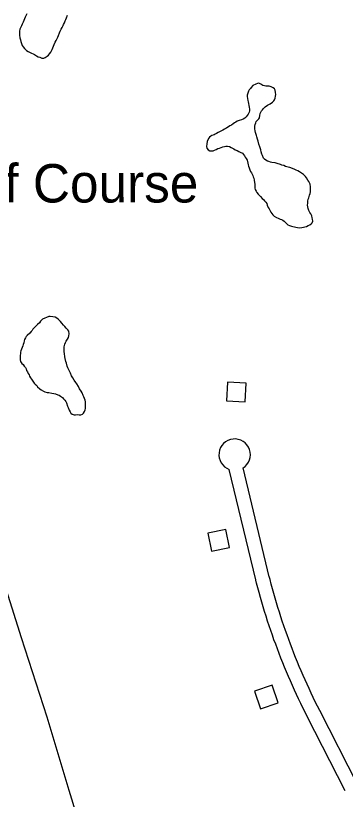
# Model space of a CAD drawing. Extents: x 3683402 to 3721514, y 487807 to 513565.
# Drawn here: x 3691713 to 3692425, y 494928 to 496621 of the extents above; entities that cross this region are included whole.
import ezdxf

# ---------------------------------------------------------------- set-up
doc = ezdxf.new("R2010")
doc.units = 0
for name, color, linetype in [('V-BLDG-IDEN', 7, 'Continuous'), ('V-BLDG-OTLN', 7, 'Continuous'), ('V-ROAD-CNTR', 7, 'Continuous'), ('V-TOPO-SHOR', 7, 'Continuous')]:
    doc.layers.add(name, color=color, linetype=linetype)

msp = doc.modelspace()

# ---------------------------------------------------------------- linework, layer by layer
at = {"layer": 'V-BLDG-OTLN'}
for points in [[(3692168.7, 495789), (3692208.7, 495786.7), (3692210.9, 495826.7), (3692171, 495828.9)], [(3692175.2, 495471.9), (3692167.3, 495511.1), (3692128.1, 495503.1), (3692136, 495463.9)], [(3692280.3, 495136.3), (3692267.3, 495174.1), (3692229.4, 495161.2), (3692242.4, 495123.3)]]:
    msp.add_lwpolyline(points, close=True, dxfattribs=at)
at = {"layer": 'V-ROAD-CNTR'}
for points in [[(3692231.8, 495401.8), (3692174.2, 495640.7)], [(3692261, 495408.8), (3692204.3, 495643.8)], [(3692343.3, 495106.4), (3692338.5, 495115.9), (3692333.7, 495125.5), (3692329.1, 495135), (3692324.4, 495144.7), (3692319.9, 495154.3), (3692315.4, 495164), (3692311, 495173.7), (3692306.7, 495183.5), (3692302.5, 495193.3), (3692298.3, 495203.1), (3692294.2, 495213), (3692290.2, 495222.9), (3692286.3, 495232.8), (3692282.4, 495242.7), (3692278.6, 495252.7), (3692274.9, 495262.7), (3692271.2, 495272.7), (3692267.7, 495282.8), (3692264.2, 495292.9), (3692260.8, 495303), (3692257.4, 495313.1), (3692254.2, 495323.3), (3692251, 495333.5), (3692247.9, 495343.7), (3692244.9, 495353.9), (3692241.9, 495364.2), (3692239, 495374.4), (3692236.2, 495384.7), (3692233.5, 495395), (3692231.9, 495401.5)], [(3692370, 495120), (3692365.3, 495129.4), (3692360.6, 495138.7), (3692356.1, 495148.1), (3692351.5, 495157.5), (3692347.1, 495167), (3692342.7, 495176.5), (3692338.4, 495186), (3692334.2, 495195.5), (3692330.1, 495205.1), (3692326, 495214.7), (3692322, 495224.4), (3692318, 495234.1), (3692314.2, 495243.8), (3692310.4, 495253.5), (3692306.7, 495263.3), (3692303, 495273), (3692299.5, 495282.9), (3692296, 495292.7), (3692292.6, 495302.6), (3692289.2, 495312.5), (3692286, 495322.4), (3692282.8, 495332.3), (3692279.7, 495342.3), (3692276.6, 495352.3), (3692273.7, 495362.3), (3692270.8, 495372.3), (3692268, 495382.4), (3692265.2, 495392.5), (3692262.6, 495402.6), (3692260.9, 495409)], [(3692451.5, 494960.1), (3692370, 495120)], [(3692424.8, 494946.4), (3692343.3, 495106.4)]]:
    msp.add_lwpolyline(points, dxfattribs=at)
msp.add_arc((3692186.1, 495672.5), 34, 302.364, 249.4831, dxfattribs=at)
at = {"layer": 'V-TOPO-SHOR'}
for points in [[(3691736.9, 496625.3), (3691734.7, 496620.4), (3691733.5, 496617.6), (3691730.4, 496610.7), (3691728.7, 496607.2), (3691726.6, 496602.5), (3691724.9, 496599.4), (3691723.7, 496596.4), (3691721.8, 496591.6), (3691720.8, 496587.4), (3691720.8, 496583.8), (3691721.2, 496579.1), (3691721.9, 496573.4), (3691722.8, 496568.7), (3691723.5, 496565.4), (3691725.1, 496560.9), (3691726.7, 496556.6), (3691728.8, 496553.5), (3691731.7, 496550.2), (3691736.3, 496545.7), (3691739.4, 496544), (3691747.2, 496540.4), (3691750.5, 496538.7), (3691753.3, 496537.1), (3691757.5, 496534.4), (3691761.3, 496532.5), (3691764.8, 496531.1), (3691769.1, 496529.4), (3691773.6, 496529.4), (3691776.4, 496530.8), (3691780.7, 496533.6), (3691783.3, 496535.9), (3691785.9, 496538.7), (3691788.8, 496542.5), (3691791.9, 496548.1), (3691794.6, 496555), (3691796.2, 496558.7), (3691798.4, 496563.5), (3691800.3, 496567.5), (3691803.9, 496575), (3691805.4, 496578.3), (3691807.5, 496584.2), (3691809, 496587.3), (3691811.1, 496592), (3691813, 496595.5), (3691815, 496599.5), (3691816.2, 496602.3), (3691818.1, 496605.9), (3691820, 496609.9), (3691821.2, 496612.9), (3691822.6, 496616.7), (3691824.8, 496621.9)], [(3692225.5, 496470.2), (3692222, 496466), (3692220.1, 496463.4), (3692217.2, 496460.8), (3692216, 496458), (3692214.3, 496454), (3692213.3, 496449.5), (3692213.3, 496446.2), (3692214, 496441.9), (3692214.7, 496437.9), (3692215.6, 496434.6), (3692215.8, 496431.5), (3692216.7, 496427), (3692217.2, 496423.7), (3692218.1, 496419.2), (3692218.1, 496415.7), (3692217.3, 496412.4), (3692215.2, 496408.4), (3692213.3, 496405.1), (3692211.4, 496402.2), (3692208.3, 496399.4), (3692204.7, 496397.3), (3692200.7, 496395.9), (3692196.2, 496394.3), (3692191.9, 496392.9), (3692188.4, 496391), (3692185.5, 496389.6), (3692182.7, 496387.1), (3692179.3, 496384.7), (3692176, 496382.9), (3692173.2, 496381), (3692169.6, 496378.9), (3692167, 496377.3), (3692163.9, 496375.6), (3692160.3, 496373.5), (3692157.5, 496371.9), (3692154.7, 496370.7), (3692150.2, 496368.6), (3692147.1, 496366.8), (3692144.2, 496365.4), (3692141.6, 496363.7), (3692137.1, 496361.9), (3692134.3, 496360.5), (3692131.6, 496358.4), (3692129.3, 496355.5), (3692126.6, 496349.2), (3692125.9, 496344.4), (3692125.1, 496338.5), (3692125.8, 496334.8), (3692128.6, 496331.4), (3692132.2, 496329.3), (3692135.9, 496329), (3692139.5, 496329.2), (3692142.8, 496330.6), (3692145.9, 496331.8), (3692149.7, 496333.9), (3692153.2, 496334.8), (3692160.3, 496337.8), (3692163.9, 496338.7), (3692167.4, 496339.4), (3692171, 496339.2), (3692174.8, 496338.2), (3692178.5, 496336.5), (3692181.4, 496335.1), (3692184.4, 496333.2), (3692187.5, 496331.5), (3692191.5, 496329.6), (3692195.2, 496327.9), (3692198.3, 496326.2), (3692202.8, 496323.8), (3692205.6, 496321.2), (3692207.7, 496318.4), (3692209.1, 496315.5), (3692210.7, 496312.2), (3692213.1, 496309.1), (3692213.8, 496305.8), (3692214.7, 496302.5), (3692215.6, 496298.9), (3692216.3, 496295.6), (3692217.2, 496292.5), (3692218.8, 496287.8), (3692220.7, 496284.7), (3692222.6, 496281.6), (3692224, 496278.8), (3692225.6, 496275.9), (3692226.5, 496272.8), (3692227.7, 496269.8), (3692228.6, 496265.3), (3692229.1, 496260.8), (3692229.5, 496257.2), (3692229.5, 496252.7), (3692229.7, 496248.7), (3692230.8, 496245.2), (3692232.7, 496241.8), (3692234.3, 496239.2), (3692236.9, 496235.7), (3692239.7, 496232.3), (3692241.8, 496230.2), (3692245.6, 496226.4), (3692248.4, 496224), (3692251, 496220.7)], [(3692240.2, 496400.6), (3692240.7, 496405.6), (3692241.4, 496409.6), (3692244.3, 496415.5), (3692246.2, 496417.8), (3692248.4, 496420.4), (3692252.2, 496424.2), (3692257.4, 496427.7), (3692263.1, 496430.7), (3692268.3, 496434.2), (3692271.2, 496436.8), (3692272.4, 496439.6), (3692273.6, 496442.5), (3692274.8, 496447.2), (3692275.3, 496450.7), (3692274.8, 496455.2), (3692273.9, 496460.2), (3692272.1, 496462.8), (3692269.7, 496464.9), (3692265, 496467.3), (3692261, 496468.5), (3692257.2, 496468.6), (3692253.7, 496469.1), (3692250.4, 496469.6), (3692247.1, 496470.3), (3692243.1, 496472.9), (3692240, 496474.6), (3692236.7, 496474.9), (3692230.3, 496472.1), (3692227, 496470.7), (3692225.5, 496470.2)], [(3692251, 496220.7), (3692253.3, 496217.8), (3692255.7, 496215), (3692256.8, 496211.7), (3692258.9, 496206.9), (3692260.8, 496203.6), (3692262.4, 496200.7), (3692264.5, 496196.5), (3692266.2, 496193.9), (3692268.5, 496190.8), (3692271.6, 496187.9), (3692276.7, 496185), (3692280, 496183.4), (3692284.3, 496181.7), (3692287.6, 496180.5), (3692290.4, 496179), (3692293, 496177.4), (3692295.8, 496174), (3692298.2, 496171.9), (3692301.4, 496169.3), (3692304.5, 496167.8), (3692308.8, 496166.2), (3692318.4, 496164.2), (3692322.4, 496163.5), (3692326, 496163), (3692331.7, 496163.4), (3692334.7, 496163.8), (3692337.8, 496164.5), (3692341.4, 496165.9), (3692344.9, 496167.6), (3692348.7, 496169.4), (3692351.8, 496171.1), (3692353.9, 496173.4), (3692355.2, 496176.9), (3692354.7, 496181.2), (3692354, 496184.5), (3692352.9, 496188.5), (3692350.8, 496192.6), (3692348.9, 496195.9), (3692346.6, 496200.4), (3692344.9, 496204.4), (3692344.5, 496207.7), (3692344, 496211.8), (3692344.1, 496216.3), (3692344.3, 496220.3), (3692345.1, 496224.5), (3692346.3, 496227.8), (3692348, 496233), (3692349.4, 496237), (3692350.2, 496240.3), (3692350.4, 496247.6), (3692350.2, 496251), (3692349.3, 496256.9), (3692347.7, 496259.7), (3692346.3, 496262.6), (3692344.4, 496265.9), (3692341.4, 496270.4), (3692339, 496273.5), (3692336.9, 496275.6), (3692335.1, 496278), (3692330.4, 496281.1), (3692326.6, 496283.5), (3692322.8, 496285.7), (3692319, 496287.6), (3692316, 496289), (3692311.5, 496290.7), (3692305.4, 496292.9), (3692301.8, 496294.1), (3692296.4, 496295.5), (3692292.6, 496297), (3692288.2, 496298.4), (3692285.1, 496299.4), (3692277.8, 496301.8), (3692273.8, 496302.8), (3692266.9, 496304), (3692263.4, 496304.7), (3692260.1, 496305.7), (3692257, 496306.9), (3692253.7, 496308.6), (3692250.9, 496311.2), (3692248.6, 496313.3), (3692246.5, 496318.6), (3692244.8, 496321.9), (3692243.2, 496326.6), (3692242.5, 496331.3), (3692240.5, 496338), (3692238.8, 496343.2), (3692236.8, 496350.1), (3692235.8, 496354.1), (3692234.2, 496359.1), (3692233.3, 496362.1), (3692231.5, 496368.3), (3692230.8, 496372.3), (3692229.9, 496376.8), (3692229.7, 496382.5), (3692230.2, 496385.6), (3692231.6, 496389.6), (3692232.8, 496392.6), (3692235.7, 496395.2), (3692238.5, 496398), (3692240.2, 496400.6)], [(3691506.3, 495963.6), (3691515.7, 495938.6), (3691546.1, 495834.6), (3691584.3, 495721.2), (3691603.6, 495662.8), (3691606.6, 495652.1), (3691605.8, 495646.5), (3691607.5, 495640), (3691609.5, 495636.8), (3691610.7, 495634.7), (3691637.6, 495545.7), (3691679.7, 495419.2), (3691724.2, 495277.1), (3691779.7, 495106.2), (3691827.6, 494947.8), (3691844.2, 494893.2)], [(3691770.9, 495965.4), (3691768.3, 495963.3), (3691766.4, 495960.7), (3691764, 495957.7), (3691760, 495953.7), (3691757.6, 495951.3), (3691755, 495948.5), (3691752.1, 495945.7), (3691750, 495943.6), (3691748.1, 495941), (3691746.2, 495938.7), (3691743.1, 495935.4), (3691737.8, 495930.2), (3691735.7, 495927.9), (3691734, 495924.8), (3691732.1, 495921.3), (3691730.9, 495918.2), (3691730.4, 495914.4), (3691729.2, 495910.9), (3691727.8, 495907.4), (3691726.6, 495903.8), (3691725.4, 495900.5), (3691724.1, 495897), (3691723.4, 495893.9), (3691722.9, 495890.6), (3691722.7, 495887.3), (3691722.4, 495883.3), (3691722.1, 495877.4), (3691723, 495873.6), (3691725.9, 495869.8), (3691728.9, 495867.2), (3691731.2, 495863.8), (3691734.1, 495861), (3691735.2, 495858.1), (3691736.4, 495854.6), (3691738.2, 495851.3), (3691739.9, 495848.2), (3691741.5, 495845.3), (3691742.9, 495842), (3691744.8, 495838.7), (3691746.6, 495835.4), (3691751.1, 495829.4), (3691753, 495827.1), (3691755.1, 495824.9), (3691758.1, 495822.1), (3691760.2, 495819), (3691764.9, 495814.9), (3691768, 495812.8), (3691772.7, 495809.9), (3691775.5, 495808.5), (3691780.7, 495807), (3691784.5, 495806.5), (3691790.9, 495805.5), (3691795.1, 495804.8), (3691798.7, 495804), (3691804.1, 495802.1), (3691806.9, 495800.9), (3691809.7, 495799), (3691813.7, 495795.7), (3691816.1, 495793.3), (3691818.7, 495790.4), (3691821, 495787.1), (3691822.2, 495784.3), (3691824.9, 495777.4), (3691825.9, 495774.3), (3691828.2, 495768.6), (3691830.3, 495764.8), (3691831.7, 495762), (3691834.5, 495759.8), (3691838.8, 495758.4), (3691842.3, 495758.6), (3691845.6, 495759.1), (3691850.1, 495758.6), (3691853.9, 495758.5), (3691857.2, 495759.7), (3691859.3, 495762.3), (3691861.5, 495765.8), (3691862.7, 495769.1), (3691863.7, 495772.6), (3691863.9, 495775.9), (3691864, 495779.5), (3691864, 495783.5), (3691863.5, 495786.8), (3691862.9, 495790.1), (3691861.5, 495793.7), (3691860.3, 495797.2), (3691858.7, 495800.6), (3691856.1, 495806.3), (3691854.2, 495809.6), (3691850.7, 495815), (3691848.2, 495819.5), (3691844.9, 495825.5), (3691843, 495828.6), (3691839.3, 495833.3), (3691836.2, 495838.5), (3691833.7, 495842.8), (3691830.9, 495848.5), (3691828.1, 495854.2), (3691825.8, 495860.1), (3691824.1, 495864.1), (3691822.3, 495870.5)], [(3691822.3, 495870.5), (3691821.4, 495874.1), (3691819.8, 495880.2), (3691819.3, 495883.6), (3691818.2, 495891.4), (3691817.7, 495894.7), (3691817.3, 495902.5), (3691817.8, 495905.8), (3691818.8, 495911.2), (3691820.5, 495915.2), (3691822.1, 495918), (3691824.8, 495921.8), (3691826.7, 495925.6), (3691827.9, 495929.1), (3691828.4, 495933.4), (3691827.5, 495939.5), (3691825.6, 495942.1), (3691822.1, 495946.2), (3691818.8, 495949.5), (3691816.2, 495952.6), (3691812.7, 495956.6), (3691809.7, 495960), (3691807.1, 495962.3), (3691804.3, 495965.4), (3691801.5, 495967.6), (3691797.9, 495969.3), (3691793.2, 495970.2), (3691787.3, 495970.8), (3691784.2, 495970.8), (3691770.9, 495965.4)]]:
    msp.add_lwpolyline(points, dxfattribs=at)

# ---------------------------------------------------------------- texts
at = {"layer": 'V-BLDG-IDEN'}
msp.add_text('Golf Course', height=83, dxfattribs=at).set_placement((3691515.5, 496217.4))

doc.saveas('drawing.dxf')
